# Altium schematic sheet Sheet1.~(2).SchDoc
size A4; SheetNumber: 2; SheetTotal: 2
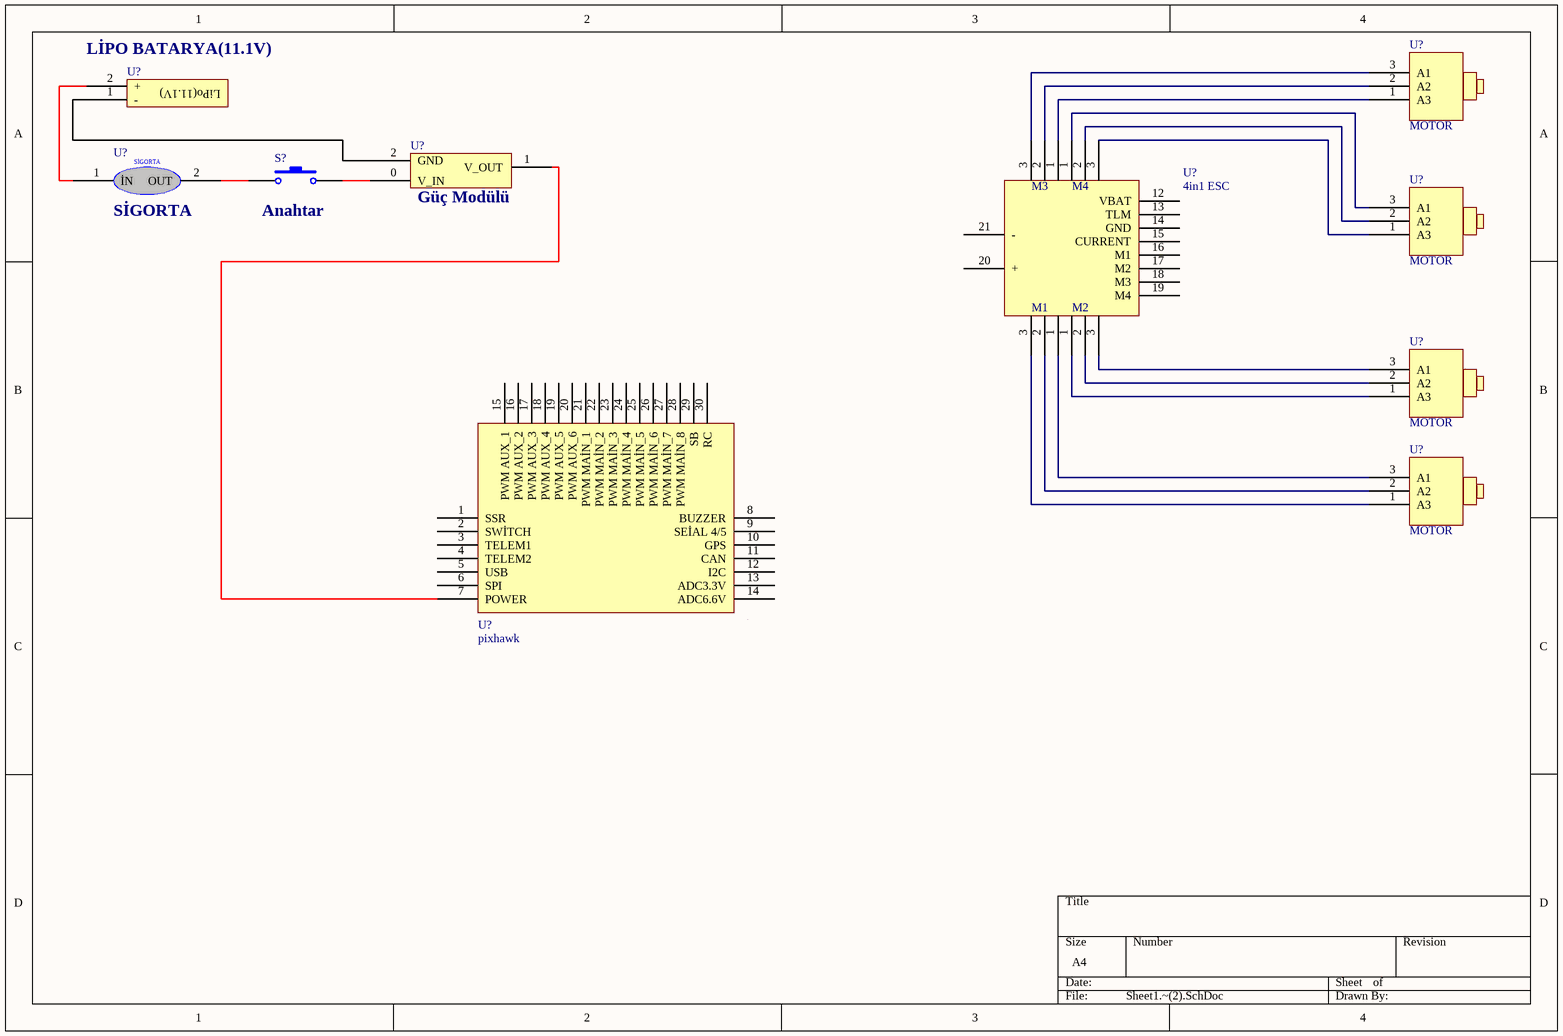
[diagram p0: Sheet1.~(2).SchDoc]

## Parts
(Parts that share a designator on the sheet are numbered #1, #2 ... from top to bottom, then left to right.)
S?  Anahtar  [SPST-2]
U?#1  pixhawk
U?#2  LİPO BATARYA(11.1V)
U?#3  MOTOR
U?#4  GÜÇ MODÜLÜ  (value not drawn)
U?#5  SİGORTA
U?#6  4in1 ESC
U?#7  MOTOR
U?#8  MOTOR
U?#9  MOTOR

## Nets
NetS?_1: S?.1 U?#5.2(OUT)
NetS?_2: S?.2 U?#4.0(V_IN)
NetU?#1_7: U?#1.7(POWER) U?#4.1(V_OUT)
NetU?#2_1: U?#2.1(-) U?#4.2(GND)
NetU?#2_2: U?#2.2(+) U?#5.1(İN)
NetU?#3_1: U?#3.1(A3) U?#6.1
NetU?#3_2: U?#3.2(A2) U?#6.2
NetU?#3_3: U?#3.3(A1) U?#6.3
NetU?#6_1: U?#6.1 U?#8.1(A3)
NetU?#6_1: U?#6.1 U?#9.3(A1)  [a separate net that carries the same name]
NetU?#6_1: U?#6.1 U?#7.3(A1)  [a separate net that carries the same name]
NetU?#6_2: U?#6.2 U?#8.2(A2)
NetU?#6_2: U?#6.2 U?#9.2(A2)  [a separate net that carries the same name]
NetU?#6_2: U?#6.2 U?#7.2(A2)  [a separate net that carries the same name]
NetU?#6_3: U?#6.3 U?#8.3(A1)
NetU?#6_3: U?#6.3 U?#9.1(A3)  [a separate net that carries the same name]
NetU?#6_3: U?#6.3 U?#7.1(A3)  [a separate net that carries the same name]

Not connected (* = marked no-connect by the designer): U?#1 1(SSR) 2(SWİTCH) 3(TELEM1) 4(TELEM2) 5(USB) 6(SPI) 8(BUZZER) 9(SEİAL_4/5) 10(GPS) 11(CAN) 12(I2C) 13(ADC3.3V) 14(ADC6.6V) 15(PWM_AUX_1) 16(PWM_AUX_2) 17(PWM_AUX_3) 18(PWM_AUX_4) 19(PWM_AUX_5) 20(PWM_AUX_6) 21(PWM_MAİN_1) 22(PWM_MAİN_2) 23(PWM_MAİN_3) 24(PWM_MAİN_4) 25(PWM_MAİN_5) 26(PWM_MAİN_6) 27(PWM_MAİN_7) 28(PWM_MAİN_8) 29(SB) 30(RC); U?#6 12(VBAT) 13(TLM) 14(GND) 15(CURRENT) 16(M1) 17(M2) 18(M3) 19(M4) 20(+) 21(-)

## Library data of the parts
S? = SW-PB: Switch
